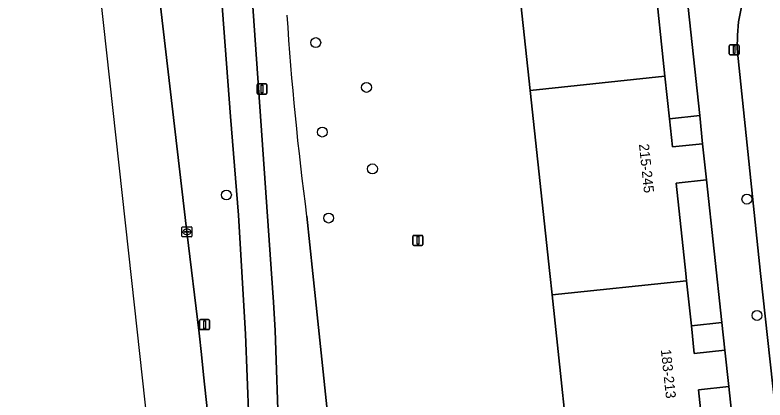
# Model space of a CAD drawing. Extents: x 161248 to 161848, y 384871 to 385383.
# Drawn here: x 161247.5 to 161322, y 385237.5 to 385275.6 of the extents above; entities that cross this region are included whole.
import ezdxf

# ---------------------------------------------------------------- set-up
doc = ezdxf.new("R2010")
doc.units = 0
for name, color, linetype in [('IMGEO_Berm_groen', 7, 'Continuous'), ('IMGEO_Boom', 7, 'Continuous'), ('IMGEO_Erf', 7, 'Continuous'), ('IMGEO_Fietspad_gesloten', 7, 'Continuous'), ('IMGEO_Kolk', 7, 'Continuous'), ('IMGEO_Lichtmast', 7, 'Continuous'), ('IMGEO_OVBaan_gesloten', 7, 'Continuous'), ('IMGEO_Pand', 7, 'Continuous'), ('IMGEO_Pand_nummerreeks', 7, 'Continuous'), ('IMGEO_Rijbaan_lokaal_open', 7, 'Continuous'), ('IMGEO_Vlaggenmast', 7, 'Continuous'), ('IMGEO_Voetpad_open', 7, 'Continuous')]:
    doc.layers.add(name, color=color, linetype=linetype)

msp = doc.modelspace()

# ---------------------------------------------------------------- linework, layer by layer
at = {"layer": 'IMGEO_Berm_groen'}
for points in [[(161279.435, 385144.415), (161273.278, 385201.438), (161272.519, 385207.639), (161271.091, 385227.08), (161270.412, 385243.981), (161269.728, 385255.799), (161268.918, 385265.585), (161266.954, 385291.9), (161266.061, 385304.636), (161265.987, 385305.638), (161262.952, 385305.408), (161262.443, 385312.634), (161261.74, 385322.607), (161257.138, 385322.371)], [(161256.654, 385321.916), (161257.172, 385317.445), (161257.661, 385313.23), (161259.702, 385295.859), (161261.967, 385276.513), (161264.604, 385254.141), (161265.807, 385244.078), (161266.037, 385241.979), (161266.267, 385239.966), (161268.56, 385218.577), (161268.655, 385216.841), (161268.939, 385214.138), (161270.794, 385196.453), (161276.441, 385144.086), (161283.784, 385075.774), (161285.879, 385056.617), (161288.02, 385037.301), (161290.772, 385012.005), (161294.901, 384976.402), (161297.066, 384956.529), (161299.154, 384937.372), (161301.048, 384920.049), (161301.427, 384916.232), (161301.431, 384916.18)]]:
    msp.add_lwpolyline(points, dxfattribs=at)
at = {"layer": 'IMGEO_Boom'}
for centre in [(161277.4, 385272.909), (161282.438, 385268.465), (161278.051, 385264.033), (161283.03, 385260.386), (161268.528, 385257.797), (161320.211, 385257.385), (161278.676, 385255.506), (161321.222, 385245.847)]:
    msp.add_circle(centre, 0.489, dxfattribs=at)
at = {"layer": 'IMGEO_Erf'}
for points in [[(161284.477, 385197.232), (161310.083, 385200.098), (161309.688, 385204.102), (161305.612, 385203.671), (161303.041, 385227.599), (161300.862, 385247.882), (161300.635, 385250), (161298.683, 385268.166), (161296.504, 385288.449), (161294.324, 385308.738), (161288.275, 385308.207), (161286.821, 385329.479), (161286.103, 385329.226), (161273.068, 385324.219)], [(161276.496, 385255.684), (161277.097, 385250), (161282.519, 385198.698)]]:
    msp.add_lwpolyline(points, dxfattribs=at)
msp.add_arc((161574.601, 385295.138), 300.705, 183.71702, 187.5393, dxfattribs=at)
at = {"layer": 'IMGEO_Fietspad_gesloten'}
for points in [[(161255.931, 385327.627), (161256.339, 385324.574), (161264.625, 385325.002), (161264.745, 385322.761), (161265.427, 385312.935), (161265.987, 385305.638), (161266.061, 385304.636), (161266.954, 385291.9), (161268.918, 385265.585), (161269.728, 385255.799), (161270.412, 385243.981), (161271.091, 385227.08), (161272.519, 385207.639), (161273.278, 385201.438), (161279.435, 385144.415), (161286.649, 385075.675), (161292.634, 385023.456), (161298.845, 384967.161), (161304.157, 384919.005), (161304.284, 384917.771), (161304.405, 384916.554)], [(161273.759, 385232.624), (161273.728, 385233.583), (161273.373, 385244.368), (161273.192, 385247.17), (161268.965, 385307.719), (161268.099, 385319.33), (161267.892, 385321.322)]]:
    msp.add_lwpolyline(points, dxfattribs=at)
at = {"layer": 'IMGEO_Kolk'}
for p, q in [((161264.178, 385254.641), (161265.03, 385254.641)), ((161264.103, 385253.715), (161264.103, 385254.567)), ((161264.362, 385254.135), (161264.362, 385254.147)), ((161264.8, 385254.098), (161264.402, 385254.098)), ((161264.405, 385254.184), (161264.803, 385254.184)), ((161264.591, 385254.421), (161264.616, 385254.421)), ((161264.846, 385254.147), (161264.846, 385254.135)), ((161265.104, 385254.567), (161265.104, 385253.715)), ((161265.03, 385253.641), (161264.178, 385253.641)), ((161264.614, 385253.861), (161264.589, 385253.861))]:
    msp.add_line(p, q, dxfattribs=at)
for points in [[(161264.178, 385254.641), (161265.03, 385254.641)], [(161264.103, 385253.715), (161264.103, 385254.567)], [(161265.104, 385254.567), (161265.104, 385253.715)], [(161265.03, 385253.641), (161264.178, 385253.641)]]:
    msp.add_lwpolyline(points, dxfattribs=at)
for centre, radius, start, end in [((161264.18, 385254.565), 0.0765, 91.55205, 178.44795), ((161264.18, 385254.565), 0.0765, 91.55205, 178.44795), ((161265.028, 385254.565), 0.0765, 1.55205, 88.44795), ((161265.028, 385254.565), 0.0765, 1.55205, 88.44795), ((161264.402, 385254.144), 0.0403, 85.87752, 175.75265), ((161264.399, 385254.134), 0.0366, 178.93798, 274.71019), ((161264.803, 385254.141), 0.043, 264.86636, 352.45326), ((161264.807, 385254.146), 0.0386, 1.73085, 96.63898), ((161264.18, 385253.717), 0.0765, 181.55205, 268.44795), ((161264.18, 385253.717), 0.0765, 181.55205, 268.44795), ((161265.028, 385253.717), 0.0765, 271.55205, 358.44795), ((161265.028, 385253.717), 0.0765, 271.55205, 358.44795)]:
    msp.add_arc(centre, radius, start, end, dxfattribs=at)
for centre, major_axis, ratio, start_param, end_param in [((161264.59, 385254.141), (-0.387, 0.002), 0.722429, 4.712389, 7.853982), ((161264.615, 385254.141), (-0.39, 0.002), 0.717154, 1.570796, 4.712389)]:
    msp.add_ellipse(centre, major_axis=major_axis, ratio=ratio, start_param=start_param, end_param=end_param, dxfattribs=at)
at = {"layer": 'IMGEO_Lichtmast'}
for p, q in [((161318.453, 385271.798), (161318.453, 385272.598)), ((161318.453, 385272.598), (161318.453, 385271.798)), ((161318.553, 385272.698), (161319.343, 385272.698)), ((161319.343, 385272.698), (161318.553, 385272.698)), ((161319.443, 385272.598), (161319.443, 385271.798)), ((161319.443, 385271.798), (161319.443, 385272.598)), ((161319.343, 385271.698), (161318.553, 385271.698)), ((161318.553, 385271.698), (161319.343, 385271.698)), ((161271.665, 385268.804), (161272.455, 385268.804)), ((161272.455, 385268.804), (161271.665, 385268.804)), ((161271.565, 385267.904), (161271.565, 385268.704)), ((161271.565, 385268.704), (161271.565, 385267.904)), ((161272.555, 385268.704), (161272.555, 385267.904)), ((161272.555, 385267.904), (161272.555, 385268.704)), ((161272.455, 385267.804), (161271.665, 385267.804)), ((161271.665, 385267.804), (161272.455, 385267.804)), ((161265.866, 385244.541), (161265.866, 385245.341)), ((161265.866, 385245.341), (161265.866, 385244.541)), ((161265.966, 385245.441), (161266.756, 385245.441)), ((161266.756, 385245.441), (161265.966, 385245.441)), ((161266.856, 385245.341), (161266.856, 385244.541)), ((161266.856, 385244.541), (161266.856, 385245.341)), ((161266.756, 385244.441), (161265.966, 385244.441)), ((161265.966, 385244.441), (161266.756, 385244.441))]:
    msp.add_line(p, q, dxfattribs=at)
for points in [[(161318.873, 385272.573), (161319.023, 385272.573), (161319.023, 385271.823), (161318.873, 385271.823), (161318.873, 385272.573)], [(161271.985, 385268.679), (161272.135, 385268.679), (161272.135, 385267.929), (161271.985, 385267.929), (161271.985, 385268.679)], [(161266.286, 385245.316), (161266.436, 385245.316), (161266.436, 385244.566), (161266.286, 385244.566), (161266.286, 385245.316)]]:
    msp.add_lwpolyline(points, dxfattribs=at)
for centre, start, end in [((161318.553, 385272.598), 90, 180), ((161318.553, 385272.598), 90, 180), ((161319.343, 385272.598), 0, 90), ((161319.343, 385272.598), 360, 90), ((161318.553, 385271.798), 180, 270), ((161318.553, 385271.798), 180, 270), ((161319.343, 385271.798), 270, 0), ((161319.343, 385271.798), 270, 0), ((161271.665, 385268.704), 90, 180), ((161271.665, 385268.704), 90, 180), ((161272.455, 385268.704), 0, 90), ((161272.455, 385268.704), 360, 90), ((161271.665, 385267.904), 180, 270), ((161271.665, 385267.904), 180, 270), ((161272.455, 385267.904), 270, 0), ((161272.455, 385267.904), 270, 0), ((161265.966, 385245.341), 90, 180), ((161265.966, 385245.341), 90, 180), ((161266.756, 385245.341), 0, 90), ((161266.756, 385245.341), 360, 90), ((161265.966, 385244.541), 180, 270), ((161265.966, 385244.541), 180, 270), ((161266.756, 385244.541), 270, 0), ((161266.756, 385244.541), 270, 0)]:
    msp.add_arc(centre, 0.1, start, end, dxfattribs=at)
at = {"layer": 'IMGEO_OVBaan_gesloten'}
msp.add_lwpolyline([(161247.533, 385354.716), (161259.107, 385249.309), (161263.048, 385213.418), (161265.088, 385213.668), (161268.939, 385214.138), (161268.655, 385216.841), (161268.56, 385218.577), (161266.267, 385239.966), (161266.037, 385241.979), (161265.807, 385244.078), (161264.604, 385254.141), (161261.967, 385276.513)], dxfattribs=at)
at = {"layer": 'IMGEO_Pand'}
for points in [[(161311.023, 385279.472), (161314.022, 385279.79), (161313.632, 385283.478), (161310.584, 385283.156), (161310.3, 385285.844), (161309.875, 385289.862), (161296.504, 385288.449), (161298.683, 385268.166), (161312.07, 385269.58)], [(161313.2, 385258.975), (161316.199, 385259.293), (161315.819, 385262.884), (161312.811, 385262.566), (161312.517, 385265.351), (161312.293, 385267.466), (161312.07, 385269.58), (161298.683, 385268.166), (161300.635, 385250), (161300.862, 385247.882), (161314.224, 385249.294), (161314.149, 385250)], [(161315.408, 385238.47), (161318.408, 385238.788), (161318.027, 385242.389), (161314.989, 385242.069), (161314.696, 385244.834), (161314.224, 385249.294), (161300.862, 385247.882), (161303.041, 385227.599), (161316.41, 385229.011)]]:
    msp.add_lwpolyline(points, close=True, dxfattribs=at)
at = {"layer": 'IMGEO_Rijbaan_lokaal_open'}
msp.add_lwpolyline([(161324.411, 385284.249), (161323.437, 385283.32), (161322.549, 385282.308), (161321.756, 385281.221), (161321.063, 385280.067), (161320.475, 385278.856), (161319.999, 385277.598), (161319.678, 385276.452), (161319.391, 385274.978), (161319.265, 385273.638), (161319.259, 385272.292), (161319.33, 385271.321), (161321.575, 385250), (161326.822, 385201.971), (161327.141, 385199.049)], dxfattribs=at)
at = {"layer": 'IMGEO_Vlaggenmast'}
for p, q in [((161287.054, 385252.892), (161287.054, 385253.692)), ((161287.054, 385253.692), (161287.054, 385252.892)), ((161287.154, 385253.792), (161287.944, 385253.792)), ((161287.944, 385253.792), (161287.154, 385253.792)), ((161288.044, 385253.692), (161288.044, 385252.892)), ((161288.044, 385252.892), (161288.044, 385253.692)), ((161287.944, 385252.792), (161287.154, 385252.792)), ((161287.154, 385252.792), (161287.944, 385252.792))]:
    msp.add_line(p, q, dxfattribs=at)
msp.add_lwpolyline([(161287.474, 385253.667), (161287.624, 385253.667), (161287.624, 385252.917), (161287.474, 385252.917), (161287.474, 385253.667)], dxfattribs=at)
for centre, start, end in [((161287.154, 385253.692), 90, 180), ((161287.154, 385253.692), 90, 180), ((161287.944, 385253.692), 0, 90), ((161287.944, 385253.692), 360, 90), ((161287.154, 385252.892), 180, 270), ((161287.154, 385252.892), 180, 270), ((161287.944, 385252.892), 270, 0), ((161287.944, 385252.892), 270, 0)]:
    msp.add_arc(centre, 0.1, start, end, dxfattribs=at)
at = {"layer": 'IMGEO_Voetpad_open'}
for points in [[(161267.892, 385321.322), (161268.099, 385319.33), (161268.965, 385307.719), (161273.192, 385247.17), (161273.373, 385244.368), (161273.728, 385233.583), (161274.951, 385233.607)], [(161312.135, 385161.71), (161328.129, 385163.466), (161330.574, 385163.733), (161326.646, 385198.993), (161327.141, 385199.049), (161326.822, 385201.971), (161321.575, 385250), (161319.33, 385271.321), (161319.259, 385272.292), (161319.265, 385273.638), (161319.391, 385274.978), (161319.678, 385276.452), (161318.759, 385276.732), (161319.247, 385278.182), (161319.902, 385279.684), (161320.689, 385281.122), (161321.6, 385282.484), (161322.63, 385283.759), (161323.77, 385284.937), (161324.411, 385284.249)], [(161314.022, 385279.79), (161315.525, 385265.669), (161315.819, 385262.884), (161316.199, 385259.293), (161317.735, 385245.154), (161318.027, 385242.389), (161318.408, 385238.788), (161319.918, 385224.889), (161320.203, 385222.192), (161320.593, 385218.503), (161321.779, 385205.407), (161321.975, 385203.771)], [(161282.519, 385198.698), (161277.097, 385250), (161276.496, 385255.684)]]:
    msp.add_lwpolyline(points, dxfattribs=at)
for points in [[(161314.022, 385279.79), (161311.023, 385279.472), (161312.07, 385269.58), (161312.293, 385267.466), (161312.517, 385265.351), (161315.525, 385265.669)], [(161315.525, 385265.669), (161312.517, 385265.351), (161312.811, 385262.566), (161315.819, 385262.884)], [(161316.199, 385259.293), (161313.2, 385258.975), (161314.149, 385250), (161314.224, 385249.294), (161314.696, 385244.834), (161317.735, 385245.154)], [(161317.735, 385245.154), (161314.696, 385244.834), (161314.989, 385242.069), (161318.027, 385242.389)], [(161318.408, 385238.788), (161315.408, 385238.47), (161316.41, 385229.011), (161316.88, 385224.568), (161319.918, 385224.889)]]:
    msp.add_lwpolyline(points, close=True, dxfattribs=at)
msp.add_arc((161574.601, 385295.138), 300.705, 183.71702, 187.5393, dxfattribs=at)

# ---------------------------------------------------------------- texts
at = {"layer": 'IMGEO_Pand_nummerreeks'}
for s, rotation, p in [('215-245', 276.06168, (161309.488, 385262.828)), ('183-213', 276.15336, (161311.663, 385242.447))]:
    msp.add_text(s, height=1, rotation=rotation, dxfattribs=at).set_placement(p)

doc.saveas('drawing.dxf')
